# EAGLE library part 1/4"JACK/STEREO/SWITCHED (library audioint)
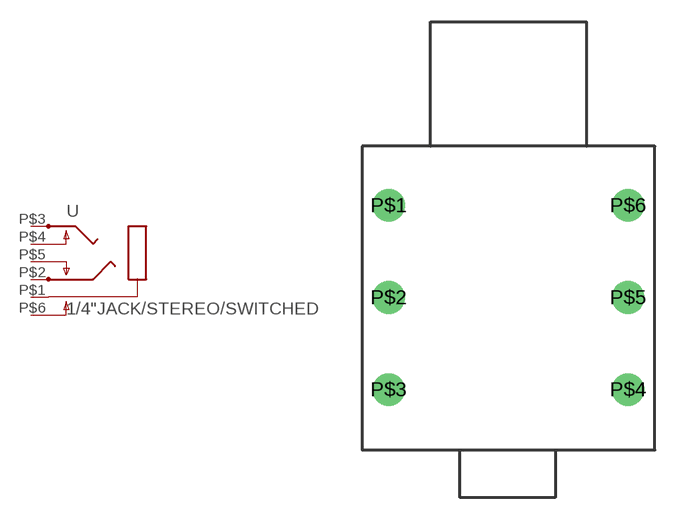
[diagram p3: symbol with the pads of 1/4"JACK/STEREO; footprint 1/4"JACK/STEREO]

Designator prefix -

## 1/4"JACK/STEREO/SWITCHEDNYS-216  [1/4"JACK/STEREO]
P$1  1  pas
P$2  2  pas
P$3  5  pas
P$4  4  pas
P$5  3  pas
P$6  6  pas

## Footprint 1/4"JACK/STEREO (pad centres in mm)
drill 1.499 round: P$1 -8.255,-4.191; P$2 -8.255,-10.541; P$3 -8.255,-16.891; P$4 8.255,-16.891; P$5 8.255,-10.541; P$6 8.255,-4.191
